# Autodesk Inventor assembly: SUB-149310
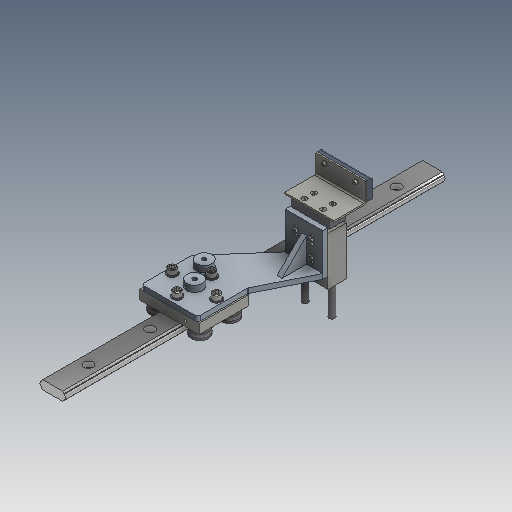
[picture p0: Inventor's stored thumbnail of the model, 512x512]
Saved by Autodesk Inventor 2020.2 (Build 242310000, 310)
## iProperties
Created: 2000-01
Part Number: SUB-149310
Document SubType Name: Assembly
Designer: sspink
Mass: 8529.21 g
Surface Area: 3534.8 cm^2
Volume: 1664.99 cm^3
Density: 5.12268 g/cm^3
Control State: 0
Checked Out: False
Master: False
Shininess: 0.0
Length Units: 11269
Angle Units: 11279
Time Units: 11290
Mass Units: 11283
Length Display Precision: 3
Angle Display Precision: 2
Compacted: True
Dimensions: 227,3x770x185,8 mm
Mass: 8,529 kg
DocNumber: SUB-149310.iam
Folder: 01 - Themengebiete\Simplification\01 - Packaging machine\
VDS_Category: 3D Komponenten
Density: 0.0
Volumn: 0.0
Area: 0.0
PropertySet Name: Model Information
Author: sspink
Revision Number: -
Title: SUB-149310
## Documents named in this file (14)
- D:\07 - DEMODATEN\OTX 2019 - Dataset - UPDATE - Dez2019\Designs\07-Packing machine\SUB-149310.iam
- D:\07 - DEMODATEN\OTX 2019 - Dataset - UPDATE - Dez2019\Designs\07-Packing machine\A105014.iam
- D:\07 - DEMODATEN\OTX 2019 - Dataset - UPDATE - Dez2019\Designs\07-Packing machine\500410R.iam
- D:\07 - DEMODATEN\OTX 2019 - Dataset - UPDATE - Dez2019\Designs\07-Packing machine\Parts\ADSK-011799.ipt
- D:\07 - DEMODATEN\OTX 2019 - Dataset - UPDATE - Dez2019\Designs\07-Packing machine\A103970.iam
- D:\07 - DEMODATEN\OTX 2019 - Dataset - UPDATE - Dez2019\Designs\07-Packing machine\Parts\ADSK-011393.ipt
- D:\07 - DEMODATEN\OTX 2019 - Dataset - UPDATE - Dez2019\Content Center Files\de-DE\ISO 10642(1)\ISO 10642 - M5x12.ipt
- D:\07 - DEMODATEN\OTX 2019 - Dataset - UPDATE - Dez2019\Content Center Files\de-DE\DIN 125-1  B\DIN 125-1 - B 5,3.ipt
- D:\07 - DEMODATEN\OTX 2019 - Dataset - UPDATE - Dez2019\Content Center Files\de-DE\ISO 4762(2)\ISO 4762 - M5 x 50ISO.ipt
- D:\07 - DEMODATEN\OTX 2019 - Dataset - UPDATE - Dez2019\Content Center Files\de-DE\ISO 4032(1)\ISO 4032 - M5DIN EN.ipt
- D:\07 - DEMODATEN\OTX 2019 - Dataset - UPDATE - Dez2019\Content Center Files\de-DE\DIN 125-1  B\DIN 125-1 - B 10,5.ipt
- D:\07 - DEMODATEN\OTX 2019 - Dataset - UPDATE - Dez2019\Content Center Files\de-DE\ISO 4762(2)\ISO 4762 - M10 x 25ISO.ipt
- D:\07 - DEMODATEN\OTX 2019 - Dataset - UPDATE - Dez2019\Designs\07-Packing machine\Parts\ADSK-011478.ipt
- D:\07 - DEMODATEN\OTX 2019 - Dataset - UPDATE - Dez2019\Content Center Files\de-DE\ISO 4762(2)\ISO 4762 - M4 x 10ISO.ipt
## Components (34 placed, 13 different names)
1. A105014:1 [sub-assembly] — Mate:1, Flush:1, Mate:2, Mate:3, Fluchtend:8
2. 500410R:1 [sub-assembly] — Mate:1, Flush:1, Flush:2, Mate:3, Mate:4, Flush:3, Flush:7, Passend:10, Passend:12, Passend:14, Passend:16
3. ADSK-011799:1 — Mate:2, Flush:3, Flush:4, Flush:5, Flush:6, Fluchtend:8
4. A103970:1 [sub-assembly] — Flush:2, Mate:4, Flush:7, Passend:17, Passend:18, Passend:19, Passend:27
5. ADSK-011393:1 — Passend:19, Passend:20, Passend:21, Passend:22, Passend:27
6. ADSK-011478:1 — Passend:20, Passend:21, Passend:22
7. DIN 125-1 B B 5,3:5 — Passend:24, Passend:26
8. DIN 125-1 B B 5,3:6
9. ISO 4762 M4 x 10:1 — Passend:24
10. ISO 4762 M4 x 10:2 — Passend:26
11. ISO 10642 M5x12:1
12. ISO 10642 M5x12:2
13. ISO 10642 M5x12:3 — Passend:17
14. ISO 10642 M5x12:4 — Passend:18
15. DIN 125-1 B B 5,3:1 — Passend:10
16. DIN 125-1 B B 5,3:2 — Passend:12
17. DIN 125-1 B B 5,3:3 — Passend:14
18. DIN 125-1 B B 5,3:4 — Passend:16
19. ISO 4762 M5 x 50:1
20. ISO 4762 M5 x 50:2
21. ISO 4762 M5 x 50:3
22. ISO 4762 M5 x 50:4
23. DIN EN 24032 M5:1
24. DIN EN 24032 M5:2
25. DIN EN 24032 M5:3
26. DIN EN 24032 M5:4
27. DIN 125-1 B B 10,5:1
28. DIN 125-1 B B 10,5:2
29. DIN 125-1 B B 10,5:3
30. DIN 125-1 B B 10,5:4
31. ISO 4762 M10 x 25:1
32. ISO 4762 M10 x 25:2
33. ISO 4762 M10 x 25:3
34. ISO 4762 M10 x 25:4
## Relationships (25: Mate 17, Flush 8)
- Mate:1: A105014:1 ↔ 500410R:1
- Flush:1: A105014:1 ↔ 500410R:1
- Mate:2: A105014:1 ↔ ADSK-011799:1
- Flush:2: 500410R:1 ↔ A103970:1
- Mate:3: A105014:1 ↔ 500410R:1
- Mate:4: 500410R:1 ↔ A103970:1
- Flush:3: 500410R:1 ↔ ADSK-011799:1
- Flush:4: ADSK-011799:1
- Flush:5: ADSK-011799:1
- Flush:6: ADSK-011799:1
- Flush:7: 500410R:1 ↔ A103970:1
- Fluchtend:8 [Flush]: A105014:1 ↔ ADSK-011799:1
- Passend:10 [Mate]: 500410R:1 ↔ DIN 125-1 B B 5,3:1
- Passend:12 [Mate]: 500410R:1 ↔ DIN 125-1 B B 5,3:2
- Passend:14 [Mate]: 500410R:1 ↔ DIN 125-1 B B 5,3:3
- Passend:16 [Mate]: 500410R:1 ↔ DIN 125-1 B B 5,3:4
- Passend:17 [Mate]: A103970:1 ↔ ISO 10642 M5x12:3
- Passend:18 [Mate]: A103970:1 ↔ ISO 10642 M5x12:4
- Passend:19 [Mate]: A103970:1 ↔ ADSK-011393:1
- Passend:20 [Mate]: ADSK-011393:1 ↔ ADSK-011478:1
- Passend:21 [Mate]: ADSK-011393:1 ↔ ADSK-011478:1
- Passend:22 [Mate]: ADSK-011393:1 ↔ ADSK-011478:1
- Passend:24 [Mate]: DIN 125-1 B B 5,3:5 ↔ ISO 4762 M4 x 10:1
- Passend:26 [Mate]: DIN 125-1 B B 5,3:5 ↔ ISO 4762 M4 x 10:2
- Passend:27 [Mate]: A103970:1 ↔ ADSK-011393:1
